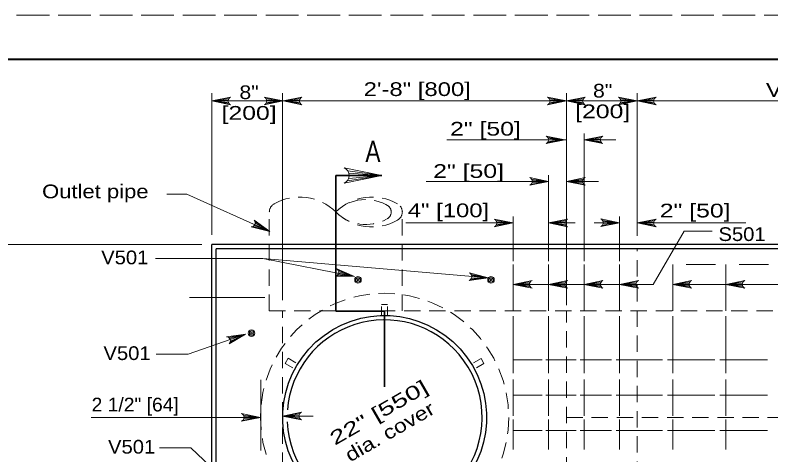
# Model space of a CAD drawing. Extents: x 758.3 to 792.3, y 849.7 to 893.7.
# Drawn here: x 762.67 to 771.26, y 888.69 to 893.69 of the extents above; entities that cross this region are included whole.
import ezdxf
from ezdxf.enums import TextEntityAlignment as Align

# ---------------------------------------------------------------- set-up
doc = ezdxf.new("R2010")
doc.units = 0
doc.header["$LTSCALE"] = 0.062
for name, pattern in [('DOTTED', [1.5, 0.3, -1.2]), ('LONG_DASHED', [7.5, 6, -1.5]), ('MEDIUM_DASHED', [4.5, 3, -1.5])]:
    doc.linetypes.add(name, pattern=pattern)
doc.layers.add('1', color=7, linetype='Continuous', lineweight=13)

msp = doc.modelspace()

# ---------------------------------------------------------------- linework, layer by layer
at = {"layer": '1', "lineweight": 25}
for p, q in [((760.3205, 893.18817), (791.8205, 893.18817)), ((776.08867, 891.08192), (764.9015, 891.08192)), ((764.9015, 887.05092), (764.9015, 891.08192)), ((776.03833, 891.0315), (764.95183, 891.0315)), ((764.95183, 887.65558), (764.95183, 891.0315))]:
    msp.add_line(p, q, dxfattribs=at)
at = {"layer": '1'}
for p, q in [((764.9015, 891.19283), (764.9015, 892.80025)), ((765.70775, 890.44908), (765.70775, 892.80025)), ((768.93292, 890.39275), (768.93292, 892.80025)), ((769.73917, 891.17917), (769.73917, 892.80025)), ((765.09533, 892.73983), (764.9015, 892.71267)), ((765.08883, 892.72642), (764.9015, 892.71267)), ((765.4615, 892.71267), (764.9015, 892.71267)), ((765.08683, 892.71267), (764.9015, 892.71267)), ((765.09025, 892.69525), (764.9015, 892.71267)), ((765.09767, 892.68275), (764.9015, 892.71267)), ((765.71358, 892.71267), (765.4615, 892.71267)), ((765.51742, 892.68275), (765.71358, 892.71267)), ((765.51975, 892.73983), (765.71358, 892.71267)), ((765.52483, 892.69525), (765.71358, 892.71267)), ((765.52625, 892.72642), (765.71358, 892.71267)), ((765.52825, 892.71267), (765.71358, 892.71267)), ((767.62767, 892.71267), (765.70775, 892.71267)), ((765.9075, 892.73983), (765.71358, 892.71267)), ((765.90092, 892.72642), (765.71358, 892.71267)), ((765.89892, 892.71267), (765.71358, 892.71267)), ((765.90233, 892.69525), (765.71358, 892.71267)), ((765.90975, 892.68275), (765.71358, 892.71267)), ((768.93292, 892.71267), (767.62767, 892.71267)), ((768.73675, 892.68275), (768.93292, 892.71267)), ((768.739, 892.73983), (768.93292, 892.71267)), ((768.74417, 892.69525), (768.93292, 892.71267)), ((768.74558, 892.72642), (768.93292, 892.71267)), ((768.74758, 892.71267), (768.93292, 892.71267)), ((769.12683, 892.73983), (768.93292, 892.71267)), ((769.12025, 892.72642), (768.93292, 892.71267)), ((769.48883, 892.71267), (768.93292, 892.71267)), ((769.11825, 892.71267), (768.93292, 892.71267)), ((769.12167, 892.69525), (768.93292, 892.71267)), ((769.12908, 892.68275), (768.93292, 892.71267)), ((769.73917, 892.71267), (769.48883, 892.71267)), ((769.543, 892.68275), (769.73917, 892.71267)), ((769.54533, 892.73983), (769.73917, 892.71267)), ((769.55042, 892.69525), (769.73917, 892.71267)), ((769.55183, 892.72642), (769.73917, 892.71267)), ((769.55383, 892.71267), (769.73917, 892.71267)), ((769.93308, 892.73983), (769.73917, 892.71267)), ((769.9265, 892.72642), (769.73917, 892.71267)), ((774.59692, 892.71267), (769.73917, 892.71267)), ((769.9245, 892.71267), (769.73917, 892.71267)), ((769.92792, 892.69525), (769.73917, 892.71267)), ((769.93533, 892.68275), (769.73917, 892.71267)), ((768.72308, 892.29783), (768.917, 892.27075)), ((768.72967, 892.28442), (768.917, 892.27075)), ((769.1345, 890.89283), (769.1345, 892.34367)), ((769.32183, 892.28383), (769.1345, 892.27008)), ((767.573, 892.27008), (768.93292, 892.27008)), ((768.72083, 892.24075), (768.917, 892.27075)), ((768.72825, 892.25333), (768.917, 892.27075)), ((768.73167, 892.27075), (768.917, 892.27075)), ((769.31983, 892.27008), (769.1345, 892.27008)), ((769.32325, 892.25267), (769.1345, 892.27008)), ((769.33067, 892.24008), (769.1345, 892.27008)), ((766.44367, 891.8055), (766.836, 891.8655)), ((766.44817, 891.91975), (766.836, 891.8655)), ((766.4585, 891.83067), (766.836, 891.8655)), ((766.46133, 891.89292), (766.836, 891.8655)), ((766.46533, 891.8655), (766.836, 891.8655)), ((768.73133, 890.89283), (768.73133, 891.8695)), ((767.34108, 891.79808), (768.73133, 891.79808)), ((768.53517, 891.76808), (768.73133, 891.79808)), ((768.53742, 891.82525), (768.73133, 891.79808)), ((768.54258, 891.78067), (768.73133, 891.79808)), ((768.544, 891.81183), (768.73133, 891.79808)), ((768.546, 891.79808), (768.73133, 891.79808)), ((769.12683, 891.82525), (768.93292, 891.79808)), ((769.12025, 891.81183), (768.93292, 891.79808)), ((769.11825, 891.79808), (768.93292, 891.79808)), ((769.12167, 891.78067), (768.93292, 891.79808)), ((769.12908, 891.76808), (768.93292, 891.79808)), ((768.93292, 891.79808), (769.29933, 891.79808)), ((765.39508, 891.33942), (765.56075, 891.23017)), ((768.13433, 891.35325), (768.32817, 891.32608)), ((768.14083, 891.33983), (768.32817, 891.32608)), ((768.32817, 890.89283), (768.32817, 891.39783)), ((768.92525, 891.35325), (768.73133, 891.32608)), ((768.91867, 891.33983), (768.73133, 891.32608)), ((769.34375, 891.35567), (769.53758, 891.3285)), ((769.35025, 891.34225), (769.53758, 891.3285)), ((769.53758, 890.89283), (769.53758, 891.39783)), ((769.93308, 891.35325), (769.73917, 891.32608)), ((769.9265, 891.33983), (769.73917, 891.32608)), ((765.37333, 891.28658), (765.56075, 891.23017)), ((765.38483, 891.29608), (765.56075, 891.23017)), ((765.39242, 891.30767), (765.56075, 891.23017)), ((765.39658, 891.32492), (765.56075, 891.23017)), ((767.10892, 891.32608), (768.32817, 891.32608)), ((768.132, 891.29608), (768.32817, 891.32608)), ((768.13942, 891.30867), (768.32817, 891.32608)), ((768.14283, 891.32608), (768.32817, 891.32608)), ((768.91667, 891.32608), (768.73133, 891.32608)), ((768.92008, 891.30867), (768.73133, 891.32608)), ((768.9275, 891.29608), (768.73133, 891.32608)), ((768.73133, 891.32608), (769.03367, 891.32608)), ((769.2475, 891.32608), (769.53758, 891.32608)), ((769.34142, 891.2985), (769.53758, 891.3285)), ((769.34883, 891.31108), (769.53758, 891.3285)), ((769.35233, 891.3285), (769.53758, 891.3285)), ((769.9245, 891.32608), (769.73917, 891.32608)), ((769.92792, 891.30867), (769.73917, 891.32608)), ((769.93533, 891.29608), (769.73917, 891.32608)), ((769.73917, 891.32608), (770.97133, 891.32608)), ((769.92042, 890.62842), (770.27008, 891.234)), ((770.27008, 891.234), (770.59, 891.234)), ((761.29283, 891.08192), (764.788, 891.08192)), ((765.48133, 890.9225), (764.26308, 890.9225)), ((768.32817, 890.32608), (768.32817, 890.85517)), ((768.73133, 890.32608), (768.73133, 890.85517)), ((769.1345, 890.32608), (769.1345, 890.85517)), ((769.53758, 890.32608), (769.53758, 890.85517)), ((770.14233, 890.32608), (770.14233, 890.85517)), ((770.294, 890.85517), (770.62742, 890.85517)), ((770.74708, 890.32608), (770.74708, 890.85517)), ((770.89875, 890.85517), (771.23217, 890.85517)), ((766.33692, 890.73942), (766.52517, 890.71692)), ((766.34125, 890.78408), (766.52517, 890.71692)), ((766.34392, 890.75575), (766.52517, 890.71692)), ((766.34483, 890.76958), (766.52517, 890.71692)), ((767.85133, 890.741), (768.043, 890.70108)), ((766.327, 890.72875), (766.52517, 890.71692)), ((767.84533, 890.68417), (768.043, 890.70108)), ((767.8535, 890.69625), (768.043, 890.70108)), ((767.857, 890.72725), (768.043, 890.70108)), ((767.85808, 890.71342), (768.043, 890.70108)), ((768.52208, 890.65558), (768.32817, 890.62842)), ((768.92525, 890.65558), (768.73133, 890.62842)), ((769.32842, 890.65558), (769.1345, 890.62842)), ((769.7315, 890.65558), (769.53758, 890.62842)), ((770.33625, 890.65558), (770.14233, 890.62842)), ((770.94092, 890.65558), (770.74708, 890.62842)), ((768.5155, 890.64217), (768.32817, 890.62842)), ((768.73133, 890.62842), (768.32817, 890.62842)), ((768.5135, 890.62842), (768.32817, 890.62842)), ((768.51692, 890.611), (768.32817, 890.62842)), ((768.52433, 890.59842), (768.32817, 890.62842)), ((768.91867, 890.64217), (768.73133, 890.62842)), ((769.1345, 890.62842), (768.73133, 890.62842)), ((768.91667, 890.62842), (768.73133, 890.62842)), ((768.92008, 890.611), (768.73133, 890.62842)), ((768.9275, 890.59842), (768.73133, 890.62842)), ((769.32183, 890.64217), (769.1345, 890.62842)), ((769.31983, 890.62842), (769.1345, 890.62842)), ((769.32325, 890.611), (769.1345, 890.62842)), ((769.33067, 890.59842), (769.1345, 890.62842)), ((769.72492, 890.64217), (769.53758, 890.62842)), ((769.72292, 890.62842), (769.53758, 890.62842)), ((769.72633, 890.611), (769.53758, 890.62842)), ((769.73383, 890.59842), (769.53758, 890.62842)), ((770.32967, 890.64217), (770.14233, 890.62842)), ((775.35458, 890.62842), (770.14233, 890.62842)), ((770.32767, 890.62842), (770.14233, 890.62842)), ((770.33108, 890.611), (770.14233, 890.62842)), ((770.3385, 890.59842), (770.14233, 890.62842)), ((770.93442, 890.64217), (770.74708, 890.62842)), ((770.93242, 890.62842), (770.74708, 890.62842)), ((770.93583, 890.611), (770.74708, 890.62842)), ((770.94325, 890.59842), (770.74708, 890.62842)), ((764.6495, 890.47725), (765.50617, 890.47725)), ((768.32817, 889.61833), (768.32817, 890.265)), ((768.73133, 889.61833), (768.73133, 890.265)), ((769.1345, 889.61833), (769.1345, 890.265)), ((769.53758, 889.61833), (769.53758, 890.265)), ((770.14233, 889.61833), (770.14233, 890.265)), ((770.74708, 889.61833), (770.74708, 890.265)), ((764.63475, 889.83308), (765.287, 890.06183)), ((765.09475, 890.0245), (765.287, 890.06183)), ((765.10533, 890.01392), (765.287, 890.06183)), ((765.11117, 889.96975), (765.287, 890.06183)), ((765.11167, 890.00158), (765.287, 890.06183)), ((765.11408, 889.984), (765.287, 890.06183)), ((764.63475, 889.83308), (764.26975, 889.83308)), ((768.65858, 889.77183), (768.32817, 889.77183)), ((769.04258, 889.77183), (768.70133, 889.77183)), ((769.4455, 889.77183), (769.09, 889.77183)), ((770.02392, 889.77183), (769.49775, 889.77183)), ((770.62125, 889.77183), (770.08075, 889.77183)), ((771.2185, 889.77183), (770.67808, 889.77183)), ((765.45842, 889.54233), (765.45842, 888.73908)), ((768.32817, 889.13333), (768.32817, 889.54533)), ((768.73133, 889.13333), (768.73133, 889.54533)), ((769.1345, 889.13333), (769.1345, 889.54533)), ((769.53758, 889.13333), (769.53758, 889.54533)), ((770.14233, 889.13333), (770.14233, 889.54533)), ((770.74708, 889.13333), (770.74708, 889.54533)), ((768.65858, 889.36875), (768.32817, 889.36875)), ((769.04258, 889.36875), (768.70133, 889.36875)), ((769.4455, 889.36875), (769.09, 889.36875)), ((770.02392, 889.36875), (769.49775, 889.36875)), ((770.62125, 889.36875), (770.08075, 889.36875)), ((771.2185, 889.36875), (770.67808, 889.36875)), ((763.531, 889.11608), (765.45583, 889.11608)), ((765.25958, 889.08608), (765.45583, 889.11608)), ((765.26192, 889.14325), (765.45583, 889.11608)), ((765.267, 889.09867), (765.45583, 889.11608)), ((765.2685, 889.12983), (765.45583, 889.11608)), ((765.2705, 889.11608), (765.45583, 889.11608)), ((765.90167, 889.15883), (765.70775, 889.13175)), ((765.89508, 889.14542), (765.70775, 889.13175)), ((765.70775, 889.13175), (766.05425, 889.13175)), ((765.89308, 889.13175), (765.70775, 889.13175)), ((765.8965, 889.11425), (765.70775, 889.13175)), ((765.90392, 889.10175), (765.70775, 889.13175)), ((768.32817, 888.75258), (768.32817, 889.09167)), ((768.73133, 888.75258), (768.73133, 889.09167)), ((769.1345, 888.75258), (769.1345, 889.09167)), ((769.53758, 888.75258), (769.53758, 889.09167)), ((770.14233, 888.75258), (770.14233, 889.09167)), ((770.74708, 888.75258), (770.74708, 889.09167)), ((768.65858, 888.96567), (768.32817, 888.96567)), ((769.04258, 888.96567), (768.70133, 888.96567)), ((769.4455, 888.96567), (769.09, 888.96567)), ((770.02392, 888.96567), (769.49775, 888.96567)), ((770.62125, 888.96567), (770.08075, 888.96567)), ((771.2185, 888.96567), (770.67808, 888.96567)), ((764.66508, 888.76933), (764.30867, 888.76933)), ((765.31725, 888.15942), (764.66508, 888.76933))]:
    msp.add_line(p, q, dxfattribs=at)
at = {"layer": '1', "lineweight": 35}
for p, q in [((766.836, 891.8655), (766.3125, 891.8655)), ((766.3125, 890.91858), (766.3125, 890.32608)), ((766.3125, 890.32542), (766.86683, 890.32542)), ((766.86683, 889.84008), (766.86683, 890.32608)), ((766.86683, 889.46233), (766.86683, 889.84008))]:
    msp.add_line(p, q, dxfattribs=at)
at = {"layer": '1', "linetype": 'MEDIUM_DASHED'}
for p, q in [((765.55658, 890.32608), (765.55658, 891.45083)), ((767.06833, 890.32608), (767.06833, 891.45083)), ((769.73917, 887.0005), (769.73917, 891.02758)), ((766.3125, 890.32608), (765.55658, 890.32608)), ((765.70775, 887.10125), (765.70775, 890.32608)), ((775.28242, 890.32608), (766.86683, 890.32608)), ((768.93292, 887.9075), (768.93292, 890.32608)), ((768.93292, 889.11675), (774.55675, 889.11675))]:
    msp.add_line(p, q, dxfattribs=at)
at = {"layer": '1', "linetype": 'DOTTED'}
for p, q in [((766.8335, 890.275), (766.8335, 890.401)), ((766.8335, 890.401), (766.90008, 890.401)), ((766.90008, 890.275), (766.90008, 890.401)), ((765.73758, 889.73), (765.77083, 889.78767)), ((765.77083, 889.78767), (765.87992, 889.72467)), ((767.96317, 889.78742), (767.854, 889.7245)), ((767.96317, 889.78742), (767.99642, 889.72983)), ((765.73758, 889.73), (765.84667, 889.667)), ((767.99642, 889.72983), (767.88725, 889.66683))]:
    msp.add_line(p, q, dxfattribs=at)
at = {"layer": '1', "linetype": 'LONG_DASHED'}
msp.add_lwpolyline([(758.3205, 871.68817), (792.3205, 871.68817), (792.3205, 893.68817), (758.3205, 893.68817)], close=True, dxfattribs=at)
at = {"layer": '1', "lineweight": 40}
msp.add_lwpolyline([(760.3205, 893.18817), (791.8205, 893.18817), (791.8205, 872.18817), (760.3205, 872.18817)], close=True, dxfattribs=at)
at = {"layer": '1'}
for points in [[(765.11567, 892.66983), (764.9015, 892.71267), (765.11567, 892.7555)], [(765.49942, 892.66983), (765.71358, 892.71267), (765.49942, 892.7555)], [(765.92775, 892.66983), (765.71358, 892.71267), (765.92775, 892.7555)], [(768.71875, 892.66983), (768.93292, 892.71267), (768.71875, 892.7555)], [(769.14708, 892.66983), (768.93292, 892.71267), (769.14708, 892.7555)], [(769.525, 892.66983), (769.73917, 892.71267), (769.525, 892.7555)], [(769.95333, 892.66983), (769.73917, 892.71267), (769.95333, 892.7555)], [(768.70283, 892.22792), (768.917, 892.27075), (768.70283, 892.31358)], [(769.34867, 892.22725), (769.1345, 892.27008), (769.34867, 892.31292)], [(769.32833, 892.29725), (769.1345, 892.27008), (769.49533, 892.27008)], [(766.40767, 891.77983), (766.836, 891.8655), (766.40767, 891.95117)], [(768.51717, 891.75525), (768.73133, 891.79808), (768.51717, 891.84092)], [(769.14708, 891.75525), (768.93292, 891.79808), (769.14708, 891.84092)], [(765.56075, 891.23017), (764.61808, 891.65192), (764.3905, 891.65192)], [(765.38408, 891.35867), (765.56075, 891.23017), (765.34833, 891.28083)], [(768.114, 891.28325), (768.32817, 891.32608), (768.114, 891.36892)], [(768.9455, 891.28325), (768.73133, 891.32608), (768.9455, 891.36892)], [(769.32342, 891.28567), (769.53758, 891.3285), (769.32342, 891.37133)], [(769.95333, 891.28325), (769.73917, 891.32608), (769.95333, 891.36892)], [(768.043, 890.70108), (765.48133, 890.9225), (766.52517, 890.71692)], [(766.30675, 890.71992), (766.52517, 890.71692), (766.32467, 890.80367)], [(767.8265, 890.67258), (768.043, 890.70108), (767.83217, 890.75808)], [(768.54233, 890.58558), (768.32817, 890.62842), (768.54233, 890.67125)], [(768.9455, 890.58558), (768.73133, 890.62842), (768.9455, 890.67125)], [(769.34867, 890.58558), (769.1345, 890.62842), (769.34867, 890.67125)], [(769.75175, 890.58558), (769.53758, 890.62842), (769.75175, 890.67125)], [(770.3565, 890.58558), (770.14233, 890.62842), (770.3565, 890.67125)], [(770.96125, 890.58558), (770.74708, 890.62842), (770.96125, 890.67125)], [(769.92042, 890.62842), (769.53758, 890.62842), (769.1345, 890.62842)], [(765.09833, 889.95175), (765.287, 890.06183), (765.0705, 890.03275)], [(765.24158, 889.07325), (765.45583, 889.11608), (765.24158, 889.15892)], [(765.92192, 889.08892), (765.70775, 889.13175), (765.92192, 889.17458)]]:
    msp.add_lwpolyline(points, dxfattribs=at)
at = {"layer": '1', "lineweight": 35}
msp.add_lwpolyline([(766.3125, 891.8655), (766.3125, 891.22308), (766.3125, 890.91858)], dxfattribs=at)
at = {"layer": '1'}
for centre, radius, start, end in [((765.13294, 892.71275), 0.04623, 112.08782, 247.91395), ((765.48214, 892.71275), 0.04623, 292.08605, 67.91218), ((765.94507, 892.71275), 0.04623, 112.08782, 247.91395), ((768.70144, 892.71275), 0.04623, 292.08605, 67.91218), ((769.16437, 892.71275), 0.04623, 112.08782, 247.91395), ((769.50773, 892.71275), 0.04623, 292.08605, 67.91218), ((769.97066, 892.71275), 0.04623, 112.08782, 247.91395), ((768.68554, 892.27079), 0.04623, 292.08605, 67.91218), ((769.36594, 892.27014), 0.04623, 112.08782, 247.91395), ((766.37307, 891.86559), 0.09245, 292.08605, 67.91218), ((768.49987, 891.79814), 0.04623, 292.08605, 67.91218), ((769.16437, 891.79814), 0.04623, 112.08782, 247.91395), ((765.35048, 891.32691), 0.04623, 267.37894, 43.20506), ((768.09673, 891.32614), 0.04623, 292.08605, 67.91218), ((768.9628, 891.32614), 0.04623, 112.08782, 247.91395), ((769.30616, 891.32857), 0.04623, 292.08605, 67.91218), ((769.97066, 891.32614), 0.04623, 112.08782, 247.91395), ((766.29882, 890.76549), 0.04623, 279.98216, 55.80829), ((767.81208, 890.71651), 0.04623, 288.27972, 64.10585), ((768.55966, 890.62847), 0.04623, 112.08782, 247.91395), ((768.9628, 890.62847), 0.04623, 112.08782, 247.91395), ((769.36594, 890.62847), 0.04623, 112.08782, 247.91395), ((769.76909, 890.62847), 0.04623, 112.08782, 247.91395), ((770.3738, 890.62847), 0.04623, 112.08782, 247.91395), ((770.97852, 890.62847), 0.04623, 112.08782, 247.91395), ((765.06805, 889.98664), 0.04623, 311.0491, 86.87523), ((765.22433, 889.11614), 0.04623, 292.08605, 67.91218), ((765.93922, 889.13176), 0.04623, 112.08782, 247.91395)]:
    msp.add_arc(centre, radius, start, end, dxfattribs=at)
at = {"layer": '1', "linetype": 'MEDIUM_DASHED'}
for centre, major_axis, ratio, start_param, end_param in [((765.90258, 891.0409), (0.57982, 0), 0.999895, 0.7853982, 2.0944916), ((766.65413, 891.10905), (-0.48317, 0), 0.999895, 4.1331408, 5.4976813), ((766.72257, 891.0409), (-0.57982, 0), 0.999895, 4.1886068, 5.4977871), ((765.66563, 891.45085), (-0.10905, 0), 0.96711, 5.2203027, 6.2831852), ((766.8515, 891.45067), (0.09087, 0), 0.96711, 5.2010124, 7.0511148), ((766.95942, 891.45085), (0.10905, 0), 0.96711, 5.2211103, 7.3447942), ((766.65413, 891.79228), (-0.48317, 0), 0.999895, 0.7852597, 2.077103), ((766.72257, 891.8608), (-0.57982, 0), 0.999895, 0.7853982, 2.094497)]:
    msp.add_ellipse(centre, major_axis=major_axis, ratio=ratio, start_param=start_param, end_param=end_param, dxfattribs=at)
at = {"layer": '1'}
for centre, major_axis in [((766.56444, 890.67881), (0.03779, 0)), ((766.56444, 890.67881), (0.0252, 0)), ((766.56444, 890.67881), (0.01008, 0)), ((768.07623, 890.67891), (0.03779, 0)), ((768.07623, 890.67886), (0.0252, 0)), ((768.07623, 890.67891), (0.01008, 0)), ((765.35501, 890.07426), (0.03779, 0)), ((765.35501, 890.07421), (0.0252, 0)), ((765.35501, 890.07426), (0.01008, 0))]:
    msp.add_ellipse(centre, major_axis=major_axis, ratio=0.999895, dxfattribs=at)
at = {"layer": '1', "linetype": 'MEDIUM_DASHED'}
msp.add_ellipse((766.8668, 889.11609), major_axis=(1.411, 0), ratio=0.999895, dxfattribs=at)
at = {"layer": '1', "lineweight": 25}
for major_axis, start_param, end_param in [((1.15904, 0), 0.6356568, 6.9188421), ((1.10864, 0), 0.7009543, 3.0642085), ((1.10864, 0), 3.1884629, 6.9841396)]:
    msp.add_ellipse((766.8668, 889.11609), major_axis=major_axis, ratio=0.999895, start_param=start_param, end_param=end_param, dxfattribs=at)

# ---------------------------------------------------------------- texts
at = {"layer": '1'}
for s, width, p in [('8"', 1.15, (765.32637, 892.73367)), ('8"', 1.15, (769.34562, 892.75108)), ('Variable 2\'-8" [0.8 m]', 1.3, (772.45933, 892.75942)), ('[200]', 1.35, (765.32646, 892.499)), ('[200]', 1.35, (769.34571, 892.51642)), ('Outlet pipe', 1.2, (763.57879, 891.60658))]:
    msp.add_text(s, height=0.156, dxfattribs=dict(at, width=width)).set_placement(p, align=Align.CENTER)
for s, height, width, p in [('2\'-8" [800]', 0.156, 1.3, (766.62883, 892.76867)), ('2" [50]', 0.156, 1.35, (767.61092, 892.31883)), ('A', 0.24, 0.8, (766.64858, 892.01958)), ('2" [50]', 0.156, 1.35, (767.41917, 891.83792)), ('4" [100]', 0.156, 1.3, (767.12992, 891.3915)), ('2" [50]', 0.156, 1.35, (769.99458, 891.38883)), ('S501', 0.156, 1.1, (770.662, 891.12092)), ('V501', 0.156, 1.1, (763.64567, 890.85633)), ('V501', 0.156, 1.1, (763.67158, 889.76833)), ('2 1/2" [64]', 0.156, 1.05, (763.53667, 889.18392)), ('V501', 0.156, 1.1, (763.7235, 888.7045))]:
    msp.add_text(s, height=height, dxfattribs=dict(at, width=width)).set_placement(p)
for s, width, p in [('22" [550]', 1.5, (766.83879, 889.10422)), ('dia. cover', 1.25, (766.96438, 888.88672))]:
    msp.add_text(s, height=0.156, rotation=29.997, dxfattribs=dict(at, width=width)).set_placement(p, align=Align.CENTER)

doc.saveas('drawing.dxf')
